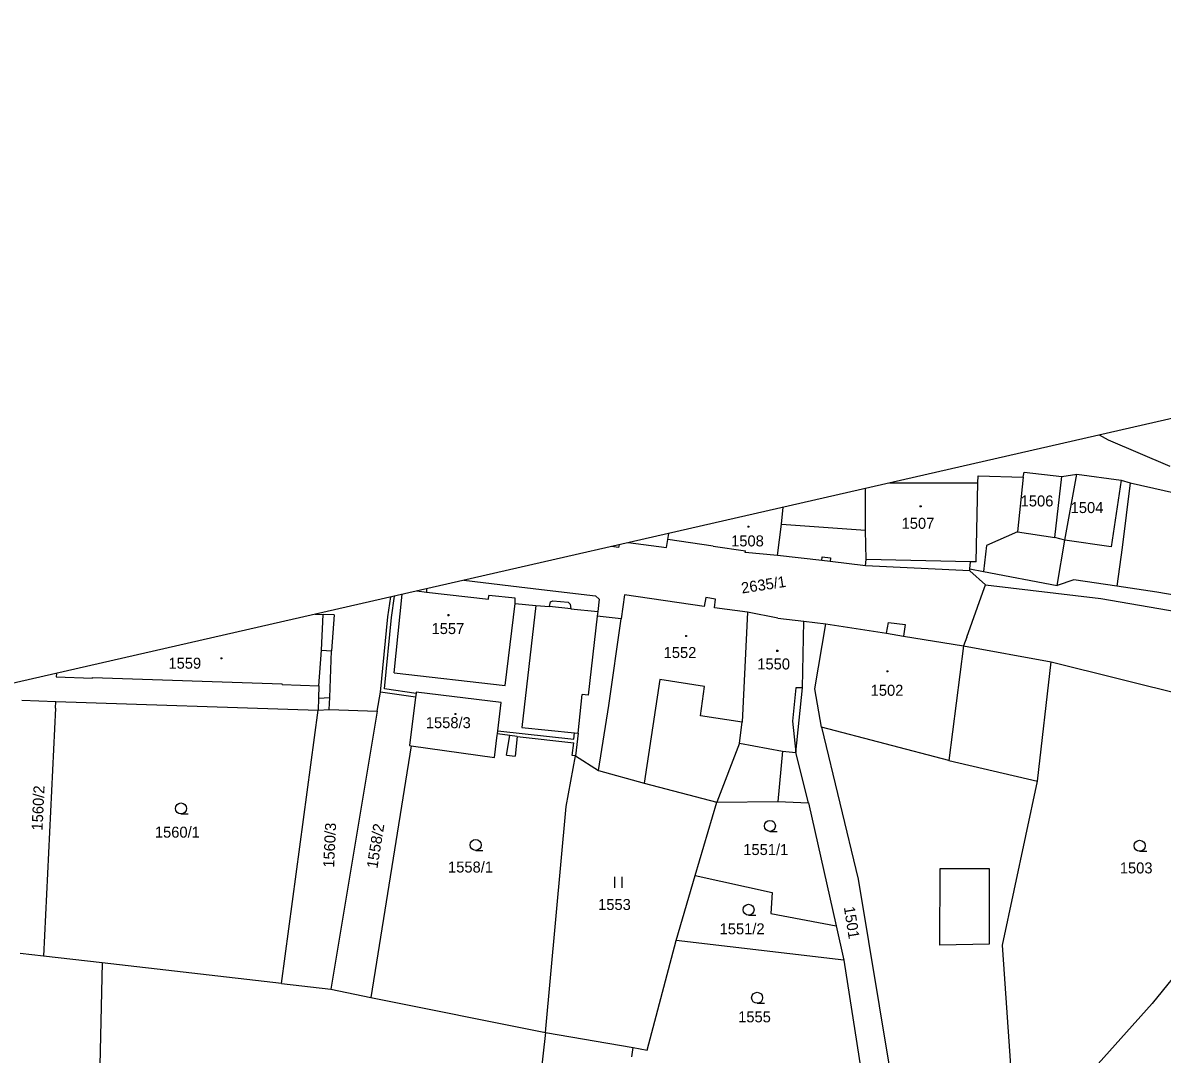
# Model space of a CAD drawing. Extents: x -805730 to -804640, y -1150889 to -1150366.
# Drawn here: x -805509 to -805353.5, y -1150600.3 to -1150459.5 of the extents above; entities that cross this region are included whole.
import ezdxf

# ---------------------------------------------------------------- set-up
doc = ezdxf.new("R2010")
doc.units = 0
for name, color, linetype in [('Default', 7, 'Continuous'), ('formát', 7, 'Continuous'), ('kn_celek - Cisla pozemkovych parcel', 7, 'Continuous'), ('kn_celek - Cisla stavebnich parcel', 7, 'Continuous'), ('kn_celek - Hranice parcel', 7, 'Continuous'), ('kn_celek - Vnitrni kresby', 7, 'Continuous'), ('kn_celek - Znacky budov', 7, 'Continuous'), ('kn_celek - Znacky kultur', 7, 'Continuous')]:
    doc.layers.add(name, color=color, linetype=linetype)

# ---------------------------------------------------------------- blocks, each defined once
blk = doc.blocks.new('304')
at = {"layer": 'Default'}
blk.add_line((-0.1, 0), (9.9, 0), dxfattribs=at)
blk.add_circle((-0.1, 7.5), 7.5, dxfattribs=at)
blk = doc.blocks.new('306')
at = {"layer": 'Default'}
for p, q in [((-5.2, 0), (-5.2, 15)), ((4.8, 0), (4.8, 15))]:
    blk.add_line(p, q, dxfattribs=at)
blk = doc.blocks.new('402')
at = {"layer": 'Default'}
for p, q in [((-0.8, 0.8), (0.7, 0.8)), ((-0.8, 0.8), (-0.8, -0.7)), ((0.7, 0.8), (0.7, -0.7)), ((0.7, -0.7), (-0.8, -0.7))]:
    blk.add_line(p, q, dxfattribs=at)

msp = doc.modelspace()

# ---------------------------------------------------------------- linework, layer by layer
at = {"layer": 'formát'}
msp.add_line((-805116.05, -1150459.54), (-805730.21, -1150599.91), dxfattribs=at)
at = {"layer": 'kn_celek - Hranice parcel'}
for p, q in [((-805362.11, -1150515.78), (-805360.88, -1150516.47)), ((-805360.88, -1150516.47), (-805352.47, -1150520.04)), ((-805378.66, -1150522.3), (-805378.64, -1150521.35)), ((-805378.64, -1150521.35), (-805372.5, -1150521.53)), ((-805372.5, -1150521.53), (-805372.33, -1150520.86)), ((-805372.33, -1150520.86), (-805367.19, -1150521.46)), ((-805367.19, -1150521.46), (-805365.15, -1150521.13)), ((-805365.15, -1150521.13), (-805359.11, -1150521.95)), ((-805390.73, -1150522.32), (-805378.66, -1150522.3)), ((-805372.5, -1150521.53), (-805373.26, -1150529.02)), ((-805368.15, -1150529.77), (-805367.19, -1150521.46)), ((-805359.11, -1150521.95), (-805357.89, -1150522.31)), ((-805357.89, -1150522.31), (-805358.96, -1150531.16)), ((-805357.89, -1150522.31), (-805328.53, -1150528.95)), ((-805394.01, -1150528.79), (-805394.01, -1150523.07)), ((-805393.89, -1150532.77), (-805394.01, -1150528.79)), ((-805373.26, -1150529.02), (-805368.15, -1150529.77)), ((-805426.38, -1150530.47), (-805421.13, -1150531.13)), ((-805421.13, -1150531.13), (-805420.95, -1150530.06)), ((-805420.95, -1150530.06), (-805420.85, -1150529.21)), ((-805414.8, -1150530.96), (-805420.95, -1150530.06)), ((-805366.81, -1150530.13), (-805368.15, -1150529.77)), ((-805367.83, -1150536.33), (-805366.81, -1150530.13)), ((-805427.7, -1150531.12), (-805428.67, -1150531)), ((-805427.62, -1150530.76), (-805427.7, -1150531.12)), ((-805414.8, -1150530.96), (-805410.39, -1150531.59)), ((-805410.42, -1150531.81), (-805410.39, -1150531.59)), ((-805405.99, -1150532.21), (-805410.42, -1150531.81)), ((-805399.97, -1150532.93), (-805405.99, -1150532.21)), ((-805358.96, -1150531.16), (-805359.71, -1150536.42)), ((-805398.82, -1150533.07), (-805399.97, -1150532.93)), ((-805393.98, -1150533.66), (-805398.82, -1150533.07)), ((-805393.98, -1150533.66), (-805393.89, -1150532.77)), ((-805379.78, -1150534.34), (-805393.98, -1150533.66)), ((-805379.78, -1150534.34), (-805379.76, -1150534.04)), ((-805377.62, -1150536.23), (-805379.78, -1150534.34)), ((-805379.76, -1150534.04), (-805377.89, -1150534.4)), ((-805377.89, -1150534.4), (-805367.83, -1150536.33)), ((-805448.8, -1150535.6), (-805442.37, -1150536.36)), ((-805442.37, -1150536.36), (-805438.22, -1150536.87)), ((-805438.22, -1150536.87), (-805430.82, -1150537.74)), ((-805377.98, -1150537.24), (-805377.62, -1150536.23)), ((-805377.62, -1150536.23), (-805361.9, -1150538.09)), ((-805365.57, -1150535.55), (-805367.83, -1150536.33)), ((-805359.71, -1150536.42), (-805365.57, -1150535.55)), ((-805354.23, -1150537.22), (-805359.71, -1150536.42)), ((-805459.17, -1150540.62), (-805458.77, -1150537.88)), ((-805430.82, -1150537.74), (-805430.33, -1150538.18)), ((-805430.33, -1150538.18), (-805430.52, -1150539.85)), ((-805426.87, -1150537.61), (-805427.33, -1150540.86)), ((-805416.02, -1150539.19), (-805426.87, -1150537.61)), ((-805415.77, -1150537.95), (-805416.02, -1150539.19)), ((-805414.46, -1150538.19), (-805415.77, -1150537.95)), ((-805414.59, -1150539.39), (-805414.46, -1150538.19)), ((-805380.18, -1150543.39), (-805377.98, -1150537.24)), ((-805361.9, -1150538.09), (-805334.75, -1150542.8)), ((-805334.31, -1150540.65), (-805354.23, -1150537.22)), ((-805430.52, -1150539.85), (-805430.6, -1150540.49)), ((-805410.1, -1150539.94), (-805414.59, -1150539.39)), ((-805410.1, -1150539.94), (-805410.81, -1150554.99)), ((-805405.98, -1150540.8), (-805410.1, -1150539.94)), ((-805460.18, -1150550.87), (-805459.17, -1150540.62)), ((-805430.6, -1150540.49), (-805431.86, -1150551.3)), ((-805427.33, -1150540.86), (-805430.6, -1150540.49)), ((-805405.98, -1150540.8), (-805402.42, -1150541.17)), ((-805402.58, -1150550.27), (-805402.42, -1150541.17)), ((-805402.42, -1150541.17), (-805399.42, -1150541.54)), ((-805400.9, -1150550.42), (-805399.42, -1150541.54)), ((-805399.42, -1150541.54), (-805391.15, -1150542.84)), ((-805391.15, -1150542.84), (-805390.87, -1150541.36)), ((-805390.87, -1150541.36), (-805388.57, -1150541.66)), ((-805388.57, -1150541.66), (-805388.82, -1150543.22)), ((-805388.82, -1150543.22), (-805380.6, -1150544.56)), ((-805380.18, -1150543.39), (-805380.6, -1150544.56)), ((-805380.6, -1150544.56), (-805368.66, -1150546.75)), ((-805370.51, -1150563.03), (-805368.66, -1150546.75)), ((-805368.66, -1150546.75), (-805328.74, -1150556.64)), ((-805460.61, -1150553.45), (-805460.18, -1150550.87)), ((-805455.39, -1150551.57), (-805460.18, -1150550.87)), ((-805455.3, -1150550.87), (-805455.32, -1150551.04)), ((-805443.69, -1150552.31), (-805455.3, -1150550.87)), ((-805403.52, -1150559.11), (-805402.58, -1150550.27)), ((-805399.98, -1150555.67), (-805400.9, -1150550.42)), ((-805509.12, -1150551.97), (-805504.5, -1150552.13)), ((-805504.54, -1150553.06), (-805504.5, -1150552.13)), ((-805504.5, -1150552.13), (-805468.7, -1150553.35)), ((-805455.39, -1150551.57), (-805456.22, -1150558.16)), ((-805455.32, -1150551.04), (-805455.39, -1150551.57)), ((-805444.17, -1150556.16), (-805443.69, -1150552.31)), ((-805433.2, -1150556.49), (-805432.65, -1150551.21)), ((-805431.86, -1150551.3), (-805432.65, -1150551.21)), ((-805504.54, -1150553.06), (-805506.16, -1150586.91)), ((-805473.68, -1150590.65), (-805468.7, -1150553.35)), ((-805468.7, -1150553.35), (-805467.17, -1150553.25)), ((-805467.17, -1150553.25), (-805460.61, -1150553.45)), ((-805460.61, -1150553.45), (-805466.95, -1150591.42)), ((-805411.2, -1150557.84), (-805410.81, -1150554.99)), ((-805444.62, -1150559.77), (-805444.24, -1150556.76)), ((-805444.24, -1150556.76), (-805444.22, -1150556.58)), ((-805444.22, -1150556.58), (-805444.17, -1150556.16)), ((-805442.51, -1150556.81), (-805444.22, -1150556.58)), ((-805442.99, -1150559.46), (-805442.51, -1150556.81)), ((-805441.51, -1150556.92), (-805441.79, -1150559.61)), ((-805441.51, -1150556.92), (-805433.8, -1150557.81)), ((-805433.2, -1150556.49), (-805433.55, -1150559.55)), ((-805399.98, -1150555.67), (-805395.01, -1150576.39)), ((-805455.99, -1150558.2), (-805461.49, -1150592.52)), ((-805456.22, -1150558.16), (-805455.99, -1150558.2)), ((-805455.99, -1150558.2), (-805444.62, -1150559.77)), ((-805434.03, -1150559.5), (-805433.8, -1150557.81)), ((-805411.2, -1150557.84), (-805414.3, -1150565.9)), ((-805442.99, -1150559.46), (-805441.79, -1150559.61)), ((-805434.86, -1150566.49), (-805433.55, -1150559.55)), ((-805433.55, -1150559.55), (-805434.03, -1150559.5)), ((-805433.55, -1150559.55), (-805430.41, -1150561.57)), ((-805401.79, -1150565.96), (-805403.52, -1150559.11)), ((-805430.41, -1150561.57), (-805424.21, -1150563.29)), ((-805424.21, -1150563.29), (-805414.3, -1150565.9)), ((-805375.32, -1150585.4), (-805370.51, -1150563.03)), ((-805331.2, -1150563.91), (-805354.86, -1150593.35)), ((-805417.22, -1150575.88), (-805414.3, -1150565.9)), ((-805414.3, -1150565.9), (-805405.97, -1150565.79)), ((-805405.97, -1150565.79), (-805401.79, -1150565.96)), ((-805401.79, -1150565.96), (-805398, -1150582.78)), ((-805437.68, -1150597.31), (-805434.86, -1150566.49)), ((-805419.83, -1150584.77), (-805417.22, -1150575.88)), ((-805417.22, -1150575.88), (-805406.71, -1150578.2)), ((-805395.01, -1150576.39), (-805390.72, -1150602.19)), ((-805406.71, -1150578.2), (-805406.9, -1150581.1)), ((-805406.9, -1150581.1), (-805398, -1150582.78)), ((-805398, -1150582.78), (-805396.94, -1150587.46)), ((-805423.81, -1150599.71), (-805419.83, -1150584.77)), ((-805396.94, -1150587.46), (-805419.83, -1150584.77)), ((-805506.16, -1150586.91), (-805509.35, -1150586.54)), ((-805373.83, -1150606.21), (-805375.32, -1150585.4)), ((-805498.17, -1150587.83), (-805506.16, -1150586.91)), ((-805498.17, -1150587.83), (-805498.93, -1150623.15)), ((-805473.68, -1150590.65), (-805498.17, -1150587.83)), ((-805396.94, -1150587.46), (-805394.39, -1150603.79)), ((-805473.68, -1150590.65), (-805466.95, -1150591.42)), ((-805466.95, -1150591.42), (-805461.49, -1150592.52)), ((-805461.49, -1150592.52), (-805437.68, -1150597.31)), ((-805354.86, -1150593.35), (-805364.74, -1150604.34)), ((-805437.68, -1150597.31), (-805443.12, -1150647.75)), ((-805437.68, -1150597.31), (-805425.71, -1150599.38)), ((-805425.86, -1150600.64), (-805425.71, -1150599.38)), ((-805425.71, -1150599.38), (-805423.81, -1150599.71))]:
    msp.add_line(p, q, dxfattribs=at)
at = {"layer": 'kn_celek - Vnitrni kresby'}
for p, q in [((-805366.81, -1150530.13), (-805365.15, -1150521.13)), ((-805378.88, -1150533.1), (-805378.66, -1150522.3)), ((-805359.11, -1150521.95), (-805360.46, -1150531.05)), ((-805405.48, -1150527.97), (-805405.25, -1150525.64)), ((-805405.99, -1150532.21), (-805405.48, -1150527.97)), ((-805405.48, -1150527.97), (-805394.01, -1150528.79)), ((-805373.26, -1150529.02), (-805377.47, -1150530.85)), ((-805360.46, -1150531.05), (-805366.81, -1150530.13)), ((-805377.47, -1150530.85), (-805377.89, -1150534.4)), ((-805399.97, -1150532.93), (-805399.91, -1150532.42)), ((-805399.91, -1150532.42), (-805398.76, -1150532.55)), ((-805398.76, -1150532.55), (-805398.82, -1150533.07)), ((-805379.68, -1150533.1), (-805393.89, -1150532.77)), ((-805379.76, -1150534.04), (-805379.68, -1150533.1)), ((-805378.88, -1150533.1), (-805379.68, -1150533.1)), ((-805453.9, -1150536.76), (-805453.89, -1150537.22)), ((-805458.68, -1150540.69), (-805458.25, -1150537.76)), ((-805458.29, -1150548.25), (-805457.21, -1150537.52)), ((-805455.22, -1150537.06), (-805453.89, -1150537.22)), ((-805453.89, -1150537.22), (-805445.44, -1150538.21)), ((-805445.44, -1150538.21), (-805445.38, -1150537.71)), ((-805441.78, -1150538.07), (-805445.38, -1150537.71)), ((-805441.79, -1150538.76), (-805441.78, -1150538.07)), ((-805436.96, -1150538.55), (-805436.65, -1150538.41)), ((-805436.65, -1150538.41), (-805434.57, -1150538.62)), ((-805443.17, -1150549.97), (-805441.79, -1150538.76)), ((-805441.79, -1150538.76), (-805438.99, -1150539.03)), ((-805438.99, -1150539.03), (-805440.91, -1150555.69)), ((-805438.99, -1150539.03), (-805437.1, -1150539.21)), ((-805437.1, -1150539.21), (-805436.96, -1150538.55)), ((-805434.2, -1150539.49), (-805437.1, -1150539.21)), ((-805434.57, -1150538.62), (-805434.31, -1150538.89)), ((-805434.31, -1150538.89), (-805434.2, -1150539.49)), ((-805434.2, -1150539.49), (-805430.52, -1150539.85)), ((-805469.09, -1150540.23), (-805468, -1150540.27)), ((-805468.22, -1150545.16), (-805468, -1150540.27)), ((-805466.52, -1150540.33), (-805468, -1150540.27)), ((-805466.52, -1150540.33), (-805466.84, -1150545.25)), ((-805459.63, -1150550.42), (-805458.68, -1150540.69)), ((-805429.02, -1150552.71), (-805427.33, -1150540.86)), ((-805391.15, -1150542.84), (-805388.82, -1150543.22)), ((-805380.6, -1150544.56), (-805382.64, -1150560.2)), ((-805468.57, -1150550.01), (-805468.22, -1150545.16)), ((-805468.22, -1150545.16), (-805466.84, -1150545.25)), ((-805467.08, -1150551.6), (-805466.84, -1150545.25)), ((-805504.41, -1150548.31), (-805504.43, -1150548.79)), ((-805504.43, -1150548.79), (-805499.48, -1150548.96)), ((-805499.48, -1150548.86), (-805473.58, -1150549.74)), ((-805499.48, -1150548.96), (-805499.48, -1150548.86)), ((-805458.29, -1150548.25), (-805443.17, -1150549.97)), ((-805422.07, -1150549.17), (-805424.21, -1150563.29)), ((-805415.98, -1150550.09), (-805422.07, -1150549.17)), ((-805473.58, -1150549.84), (-805473.58, -1150549.74)), ((-805473.58, -1150549.84), (-805468.57, -1150550.01)), ((-805468.57, -1150550.01), (-805468.62, -1150551.68)), ((-805455.32, -1150551.04), (-805459.63, -1150550.42)), ((-805416.53, -1150554.11), (-805415.98, -1150550.09)), ((-805403.49, -1150550.3), (-805403.95, -1150554.84)), ((-805402.58, -1150550.27), (-805403.49, -1150550.3)), ((-805468.62, -1150551.68), (-805468.7, -1150553.35)), ((-805468.62, -1150551.68), (-805467.08, -1150551.6)), ((-805467.17, -1150553.25), (-805467.08, -1150551.6)), ((-805430.41, -1150561.57), (-805429.02, -1150552.71)), ((-805410.81, -1150554.99), (-805416.53, -1150554.11)), ((-805403.95, -1150554.84), (-805403.52, -1150559.11)), ((-805444.17, -1150556.16), (-805433.78, -1150557.3)), ((-805441.51, -1150556.92), (-805442.51, -1150556.81)), ((-805440.91, -1150555.69), (-805433.7, -1150556.44)), ((-805433.78, -1150557.3), (-805433.7, -1150556.44)), ((-805433.7, -1150556.44), (-805433.2, -1150556.49)), ((-805382.64, -1150560.2), (-805399.98, -1150555.67)), ((-805411.2, -1150557.84), (-805405.34, -1150558.91)), ((-805405.34, -1150558.91), (-805405.97, -1150565.79)), ((-805405.34, -1150558.91), (-805403.52, -1150559.11)), ((-805382.64, -1150560.2), (-805370.51, -1150563.03)), ((-805383.83, -1150585.38), (-805383.81, -1150574.93)), ((-805383.81, -1150574.93), (-805377.12, -1150574.94)), ((-805377.12, -1150574.94), (-805377.14, -1150585.25)), ((-805377.14, -1150585.25), (-805383.83, -1150585.38))]:
    msp.add_line(p, q, dxfattribs=at)

# ---------------------------------------------------------------- block references
at = {"layer": 'kn_celek - Znacky budov', "xscale": 0.1, "yscale": 0.10000000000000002}
for p in [(-805386.48, -1150525.53), (-805409.98, -1150528.29), (-805450.91, -1150540.38), (-805418.48, -1150543.22), (-805481.89, -1150546.27), (-805406.04, -1150545.24), (-805391.02, -1150548.04), (-805449.97, -1150553.85)]:
    msp.add_blockref('402', p, dxfattribs=at)
at = {"layer": 'kn_celek - Znacky kultur', "xscale": 0.1, "yscale": 0.10000000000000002}
for name, p in [('304', (-805487.39, -1150567.5)), ('304', (-805407.03, -1150569.87)), ('304', (-805447.18, -1150572.47)), ('304', (-805356.58, -1150572.59)), ('306', (-805427.67, -1150577.58)), ('304', (-805409.94, -1150581.32)), ('304', (-805408.77, -1150593.33))]:
    msp.add_blockref(name, p, dxfattribs=at)

# ---------------------------------------------------------------- texts
at = {"layer": 'kn_celek - Cisla pozemkovych parcel'}
for s, p in [('1506', (-805372.82, -1150525.54)), ('1504', (-805366, -1150526.44)), ('1560/1', (-805490.96, -1150570.73)), ('1551/1', (-805410.67, -1150573.1)), ('1558/1', (-805450.96, -1150575.49)), ('1503', (-805359.29, -1150575.61)), ('1553', (-805430.48, -1150580.6)), ('1551/2', (-805413.9, -1150583.92)), ('1555', (-805411.37, -1150595.93))]:
    msp.add_text(s, height=1.5, dxfattribs=at).set_placement(p)
for s, rotation, p in [('2635/1', 8.6544, (-805410.83, -1150537.42)), ('1560/2', 87.3, (-805506.3, -1150569.78)), ('1560/3', 87.3, (-805466.51, -1150574.86)), ('1558/2', 81, (-805460.6, -1150575)), ('1501', 279, (-805396.96, -1150580.22))]:
    msp.add_text(s, height=1.5, rotation=rotation, dxfattribs=at).set_placement(p)
at = {"layer": 'kn_celek - Cisla stavebnich parcel'}
for s, p in [('1507', (-805389.07, -1150528.59)), ('1508', (-805412.33, -1150530.99)), ('1557', (-805453.21, -1150542.95)), ('1552', (-805421.54, -1150546.22)), ('1559', (-805489.11, -1150547.68)), ('1550', (-805408.76, -1150547.78)), ('1502', (-805393.29, -1150551.37)), ('1558/3', (-805453.99, -1150555.79))]:
    msp.add_text(s, height=1.5, dxfattribs=at).set_placement(p)

doc.saveas('drawing.dxf')
